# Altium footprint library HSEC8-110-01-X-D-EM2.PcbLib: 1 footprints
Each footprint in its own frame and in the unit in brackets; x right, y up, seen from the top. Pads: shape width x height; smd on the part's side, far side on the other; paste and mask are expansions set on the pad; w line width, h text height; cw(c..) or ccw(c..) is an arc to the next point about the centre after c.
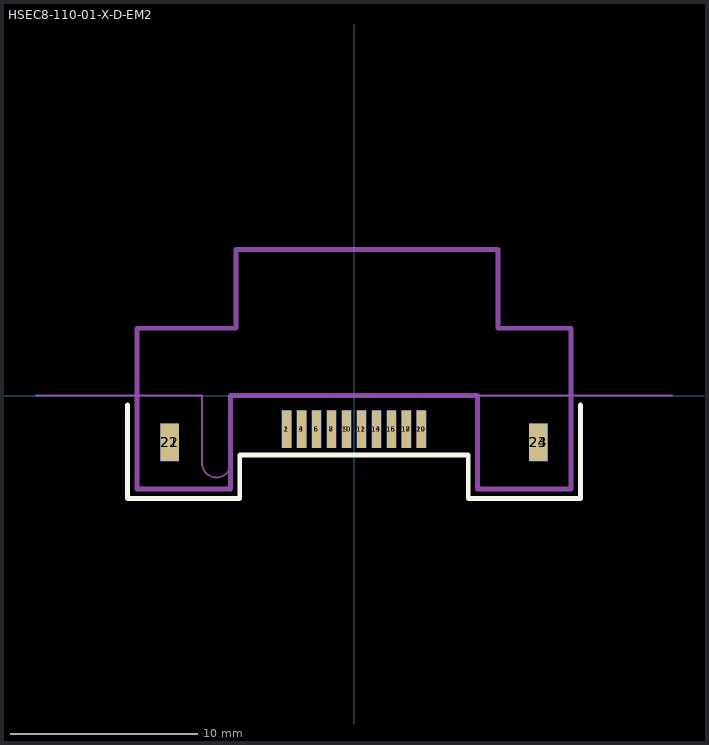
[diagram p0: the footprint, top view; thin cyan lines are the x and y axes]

## HSEC8-110-01-X-D-EM2 [mm]
pads (24):
  rect 0.5x2 smd mask+0.05: 1(-3.6,-1.8) 3(-2.8,-1.8) 5(-2,-1.8) 7(-1.2,-1.8) 9(-0.4,-1.8) 11(0.4,-1.8) 13(1.2,-1.8) 15(2,-1.8) 17(2.8,-1.8) 19(3.6,-1.8)
  rect 0.5x2 smd far side mask+0.05: 2(-3.6,-1.8) 4(-2.8,-1.8) 6(-2,-1.8) 8(-1.2,-1.8) 10(-0.4,-1.8) 12(0.4,-1.8) 14(1.2,-1.8) 16(2,-1.8) 18(2.8,-1.8) 20(3.6,-1.8)
  rect 1x2 smd mask+0.05: 21(-9.85,-2.5) 23(9.85,-2.5)
  rect 1x2 smd far side mask+0.05: 22(-9.85,-2.5) 24(9.85,-2.5)
Top Overlay:
  lines w0.254: -12.1,-0.5 -12.1,-5.5 -6.1,-5.5 -6.1,-3.18 6.1,-3.18 6.1,-5.5 12.1,-5.5 12.1,-0.5
Bottom Overlay:
  lines w0.254: -12.1,-0.5 -12.1,-5.5 -6.1,-5.5 -6.1,-3.18 6.1,-3.18 6.1,-5.5 12.1,-5.5 12.1,-0.5
Mechanical 1:
  lines w0.254: -11.6,-5 -11.6,3.6 -6.3,3.6 -6.3,7.8 7.7,7.8 7.7,3.6 11.6,3.6 11.6,-5 6.6,-5 6.6,0 -6.6,0 -6.6,-5 -11.6,-5
  text "J1" at -0.446,2.083 h0.76
Mechanical 16:
  lines w0.1: -17,0 -8.124,0 -8.124,-3.601 ccw(c-7.35,-3.601) -6.576,-3.601 -6.576,0 17,0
